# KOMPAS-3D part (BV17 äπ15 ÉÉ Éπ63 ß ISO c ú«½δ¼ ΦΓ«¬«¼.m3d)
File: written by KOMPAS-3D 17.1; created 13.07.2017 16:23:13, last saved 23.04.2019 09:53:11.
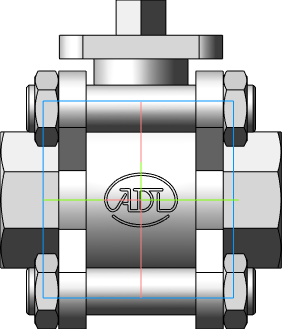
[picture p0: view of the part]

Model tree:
1. Операция без истории:2  (labels: Сталь 20  ГОСТ 1050-88)

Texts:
  DISO1
  DISO2
  BV17 Ду8 1/4" Ру63 с ISO
  BV17 Ду8 СС Ру63 с ISO
  BV17 Ду10 3/8" Ру63 с ISO
  BV17 Ду10 СС Ру63 с ISO
  BV17 Ду15 1/2" Ру63 с ISO
  BV17 Ду15 СС Ру63 с ISO
  BV17 Ду15 ФФ Ру40 с ISO
  BV17 Ду20 3/4" Ру63 с ISO
  BV17 Ду20 СС Ру40 с ISO
  BV17 Ду20 ФФ Ру40 с ISO
  BV17 Ду25 1" Ру63 с ISO
  BV17 Ду25 СС Ру63 с ISO
  BV17 Ду25 ФФ Ру40 с ISO
  BV17 Ду32 1 1/4" Ру63 с ISO
  BV17 Ду32 СС Ру63 с ISO
  BV17 Ду32 ФФ Ру40 с ISO
  BV17 Ду40 1 1/2" Ру63 с ISO
  BV17 Ду40 СС Ру63 с ISO
  BV17 Ду40 ФФ Ру40 с ISO
  BV17 Ду50 2" Ру63 с ISO
  BV17 Ду50 СС Ру63 с ISO
  BV17 Ду50 ФФ Ру40 с ISO
  BV17 Ду65 2 1/2" Ру40 с ISO
  BV17 Ду65 СС Ру40 с ISO
  BV17 Ду65 ФФ Ру40 с ISO
  BV17 Ду80 3" Ру40 с ISO
  BV17 Ду80 СС Ру40 с ISO
  BV17 Ду80 ФФ Ру40 с ISO
  BV17 Ду100 4" Ру40 с ISO
  BV17 Ду100 СС Ру40 с ISO
  BV17 Ду100 ФФ Ру40 с ISO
